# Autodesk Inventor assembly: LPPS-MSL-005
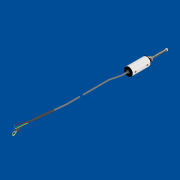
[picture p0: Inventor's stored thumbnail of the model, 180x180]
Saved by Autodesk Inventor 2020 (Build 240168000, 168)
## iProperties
Created: 2019-08
Part Number: LPPS-MSL-005
Document SubType Name: Assembly
Designer: J. Nielson
Author: J. Nielson
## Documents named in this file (5)
- D:\Users\Justin\Documents\CAD Drawings\The Sensor Connection\LPPS\LPPS-MSL\3D\LPPS-MSL-015\LPPS-MSL-005 Pack N Go\LPPS-MSL-005.iam
- D:\Users\Justin\Documents\CAD Drawings\The Sensor Connection\LPPS\LPPS-MSL\3D\LPPS-MSL-015\LPPS-MSL-005 Pack N Go\LPPS-MSL-005 Housing Assembly_SW.ipt
- D:\Users\Justin\Documents\CAD Drawings\The Sensor Connection\LPPS\LPPS-MSL\3D\LPPS-MSL-015\LPPS-MSL-005 Pack N Go\Shaft Assembly-LPPS-MSL-005_SW.ipt
- D:\Users\Justin\Documents\CAD Drawings\The Sensor Connection\LPPS\LPPS-MSL\3D\LPPS-MSL-015\LPPS-MSL-005 Pack N Go\MSL-Spring 5mm.ipt
- D:\Users\Justin\Documents\CAD Drawings\The Sensor Connection\LPPS\LPPS-MSL\3D\LPPS-MSL-015\LPPS-MSL-005 Pack N Go\ISO 4035 - M8BS EN.ipt
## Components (4 placed, 4 different names)
1. LPPS-MSL-005 Housing Assembly_SW:1 — Mate:1, Stroke, Mate:3, Mate:4, Mate:5
2. Shaft Assembly-LPPS-MSL-005_SW:1 — Mate:1, Stroke, Mate:3, Flush:1
3. MSL-Spring 5mm:1 — Flush:1
4. ISO 4035 - M8BS EN:1 — Mate:4, Angle:1, Mate:5
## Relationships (7: Mate 5, Flush 1, Angle 1)
- Mate:1: LPPS-MSL-005 Housing Assembly_SW:1 ↔ Shaft Assembly-LPPS-MSL-005_SW:1
- Stroke [Mate]: LPPS-MSL-005 Housing Assembly_SW:1 ↔ Shaft Assembly-LPPS-MSL-005_SW:1
- Mate:3: LPPS-MSL-005 Housing Assembly_SW:1 ↔ Shaft Assembly-LPPS-MSL-005_SW:1
- Flush:1: Shaft Assembly-LPPS-MSL-005_SW:1 ↔ MSL-Spring 5mm:1
- Mate:4: LPPS-MSL-005 Housing Assembly_SW:1 ↔ ISO 4035 - M8BS EN:1
- Angle:1: ISO 4035 - M8BS EN:1
- Mate:5: LPPS-MSL-005 Housing Assembly_SW:1 ↔ ISO 4035 - M8BS EN:1
